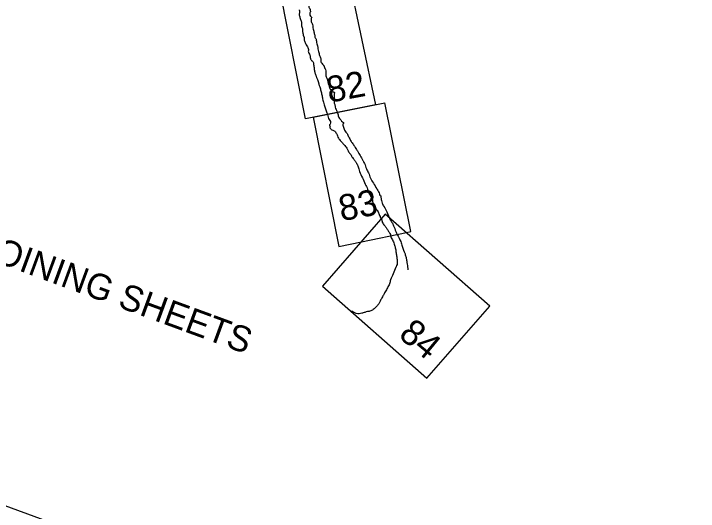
# Model space of a CAD drawing. Extents: x 3972907 to 3994831, y 172639 to 190852.
# Drawn here: x 3985354 to 3986903, y 175090 to 176216 of the extents above; entities that cross this region are included whole.
import ezdxf

# ---------------------------------------------------------------- set-up
doc = ezdxf.new("R2010")
doc.units = 0
doc.layers.add('V-ANNO-NPLT', color=7, linetype='Continuous')
doc.layers.add('V-ANNO-SYMB', color=7, linetype='Continuous')

msp = doc.modelspace()

# ---------------------------------------------------------------- linework, layer by layer
at = {"layer": 'V-ANNO-NPLT'}
for points in [[(3986110.6, 176302.8), (3986172.1, 176009.6)], [(3986172.1, 176009.6), (3986013.8, 175977.8), (3985956, 176271.3)], [(3986031.4, 175981.3), (3986193.6, 176013.9)], [(3986242.5, 175720.6), (3986252.5, 175722.7), (3986193.6, 176013.9)], [(3986031.4, 175981.3), (3986089.5, 175688.8), (3986140.4, 175699.4)], [(3986052.4, 175599.3), (3986288.5, 175391.1), (3986430.6, 175554), (3986194.4, 175762.3)], [(3986194.4, 175762.3), (3986052.4, 175599.3)], [(3986140.4, 175699.4), (3986242.5, 175720.6)]]:
    msp.add_lwpolyline(points, dxfattribs=at)
for points in [[(3986016.7, 176284.5), (3986015.7, 176281.3), (3986016.1, 176279.5), (3986016.4, 176274), (3986016.2, 176269.2), (3986016.3, 176264.6), (3986017.3, 176260.4), (3986017.7, 176257.3), (3986018.7, 176251.5), (3986020, 176246.4), (3986020.9, 176243.1), (3986021.1, 176239.5), (3986021.3, 176235.9), (3986021.3, 176230.2), (3986022.8, 176228), (3986023.8, 176227.1), (3986024.7, 176222.9), (3986024.9, 176220.1), (3986023.8, 176217.3), (3986023.4, 176214.2), (3986024.8, 176210.2), (3986026.9, 176208.5), (3986027.9, 176207.6), (3986027, 176204.7), (3986026.5, 176202.7), (3986026.4, 176200.9), (3986026.4, 176199.6)], [(3985999.6, 176224), (3986000, 176222.6), (3986000.1, 176220.7), (3986000.2, 176218.1), (3986000.1, 176217.2), (3985999.7, 176215.6)], [(3985999.7, 176215.6), (3985999.5, 176214.2), (3985999.7, 176212.5), (3986000.8, 176208.5), (3986001.8, 176204.7), (3986003.2, 176200.6), (3986004.6, 176196.8), (3986004.7, 176190.6), (3986005.8, 176185.8), (3986006.7, 176181.9), (3986007, 176179.1), (3986006.8, 176177.3)], [(3986026.4, 176199.7), (3986027.6, 176196), (3986028.8, 176193.6), (3986030.2, 176188.2), (3986030.6, 176183.7), (3986031.9, 176178.1), (3986032.8, 176174.7), (3986033.7, 176170.6), (3986034.6, 176166.8), (3986034.9, 176164.2), (3986036, 176161.3), (3986037.9, 176157.9), (3986038.2, 176155.3), (3986038.5, 176153.9)], [(3986006.8, 176177.3), (3986007.3, 176174.2), (3986007.8, 176171.2), (3986008.8, 176167.7), (3986009.1, 176165.4), (3986009.9, 176164.2)], [(3986009.9, 176164.2), (3986010.5, 176162.7), (3986010.5, 176159.2), (3986011, 176155.8), (3986012.3, 176152), (3986015.4, 176144.9), (3986018.2, 176140.8), (3986019.8, 176136.7), (3986020.6, 176133.1), (3986020, 176130.9), (3986021.6, 176126), (3986023.7, 176121.6), (3986024.3, 176118.4), (3986024.5, 176117)], [(3986038.5, 176153.9), (3986039.5, 176147.7), (3986041, 176142.5), (3986042.1, 176136.4), (3986043.5, 176130.2), (3986045.6, 176121), (3986047.8, 176115.5), (3986048.7, 176112.4), (3986048.8, 176106.5), (3986050.7, 176103.6), (3986054, 176099.6), (3986054.8, 176098.7), (3986056.6, 176097.2)], [(3986024.5, 176117), (3986024.8, 176114.9), (3986026, 176112.3), (3986027.5, 176109.9), (3986028.8, 176108.6), (3986029.9, 176107.9)], [(3986029.9, 176107.9), (3986030.4, 176107.3), (3986031.7, 176104.3), (3986032.3, 176100.3), (3986033, 176096.5), (3986033.6, 176091.2), (3986034.6, 176083.4), (3986037.1, 176076.5), (3986037.7, 176073.9), (3986040.2, 176068.6), (3986043.1, 176060.1), (3986043.7, 176057.5), (3986044.6, 176054.1), (3986045.4, 176052)], [(3986055.9, 176097.8), (3986056.4, 176095.6), (3986057.2, 176092.8), (3986059.2, 176089), (3986059.6, 176084.3), (3986059.5, 176080), (3986060, 176075), (3986061.8, 176069.9), (3986063.8, 176064.6), (3986064.7, 176060.7), (3986066.4, 176053.8), (3986067.9, 176048.6), (3986069.7, 176045), (3986072.2, 176043.7), (3986073, 176041)], [(3986045.4, 176052), (3986048.1, 176043.6), (3986050.3, 176034.6), (3986052.1, 176025.5), (3986054.6, 176015.1), (3986056.3, 176009.1), (3986059, 176000.7), (3986062.2, 175991.6), (3986063.3, 175987.4), (3986065.3, 175981.5), (3986067.1, 175976.4), (3986070.3, 175971.4), (3986069.8, 175965.9), (3986068.3, 175964.1), (3986068.7, 175961.8), (3986069.3, 175960.5)], [(3986073, 176041), (3986075.6, 176038.6), (3986077.2, 176038.5), (3986078.8, 176037.9), (3986079.2, 176036.1), (3986078.8, 176033), (3986078.8, 176029.5), (3986078.8, 176023.8), (3986078.6, 176018.5), (3986078.8, 176013.5), (3986080.9, 176007.1), (3986081, 176003.8), (3986082.9, 175999), (3986084.3, 175996.3), (3986086.1, 175991.3), (3986087.8, 175986.5), (3986088.4, 175982.5), (3986093.5, 175975.4), (3986095.5, 175972.4), (3986099.5, 175969.5)], [(3986069.3, 175960.5), (3986069.1, 175957.7), (3986070.1, 175956), (3986072.2, 175953.8), (3986078.8, 175950.7), (3986081.4, 175948.3), (3986084, 175944.3), (3986086.3, 175939.1), (3986088.6, 175934.1), (3986090.7, 175931.2), (3986094, 175926.9), (3986097.4, 175923.4), (3986099.6, 175920.7), (3986102.9, 175917.3), (3986106, 175913.4), (3986108.4, 175910), (3986109.7, 175907), (3986113.6, 175900.4), (3986115.2, 175898.9), (3986116.9, 175895.6), (3986118.9, 175891.8), (3986121.4, 175888.4), (3986124.3, 175884.9), (3986126.3, 175882.2), (3986127.6, 175880.1), (3986129.1, 175877.6), (3986129.6, 175876.9)], [(3986099.5, 175969.5), (3986099.7, 175968.8), (3986099.9, 175967.4), (3986098.6, 175965.4), (3986099.1, 175961.2), (3986100.2, 175957), (3986102.1, 175952.2), (3986105, 175947.8), (3986108.9, 175943.1), (3986110.7, 175938.8), (3986112.9, 175934.7), (3986115, 175930.4), (3986116.8, 175926.7), (3986119.4, 175923.6), (3986122.4, 175919.4), (3986126.3, 175912.8), (3986129, 175908.7), (3986131.2, 175905.2), (3986134.4, 175899.1), (3986137.9, 175894.7), (3986140.2, 175889.5), (3986143.4, 175883.9), (3986144.7, 175881.6)], [(3986144.7, 175881.6), (3986147.5, 175877), (3986151.8, 175865), (3986156.3, 175855.9), (3986160.9, 175843.3), (3986167.5, 175832.4), (3986175.1, 175819.4), (3986179.2, 175812.5), (3986181.1, 175807.7), (3986184.4, 175803.7), (3986184.8, 175803.7)], [(3986129.6, 175876.9), (3986132.7, 175869.5), (3986134.4, 175864.7), (3986136.1, 175858.7), (3986142.5, 175844.6), (3986148.8, 175830.2), (3986154.4, 175818.8), (3986157.4, 175810.1), (3986161.2, 175803.2), (3986164.4, 175796.8), (3986165.7, 175790.4)], [(3986184.6, 175803.7), (3986184.7, 175797), (3986185.5, 175793.3), (3986187, 175787.4), (3986191.4, 175779.3), (3986197.5, 175767.8), (3986201.5, 175758.7), (3986203.6, 175753.4), (3986209.2, 175743.6), (3986213.3, 175735.7), (3986218.3, 175723.2), (3986221.5, 175715.9)], [(3986165.7, 175790.4), (3986167.1, 175787.6), (3986169.1, 175784.9), (3986170.4, 175782.5), (3986171.2, 175779.6), (3986171.6, 175776.8), (3986174.7, 175772.2), (3986176.7, 175769.5), (3986179.1, 175765.2), (3986180.7, 175761.5), (3986182.4, 175757.1), (3986183.4, 175753.7), (3986185.7, 175750.9), (3986186.6, 175747.5), (3986187.6, 175744.1), (3986189.8, 175740.2), (3986192.5, 175736.5), (3986194.2, 175735.3)], [(3986194.2, 175735.3), (3986198.2, 175728.8), (3986201.7, 175723.3), (3986205.8, 175716.4), (3986207.7, 175708.8), (3986210.4, 175704.4), (3986214.2, 175694.4), (3986217, 175685.8), (3986218.5, 175677.2), (3986219.8, 175668.1), (3986220.9, 175659.7), (3986221.3, 175653), (3986220.9, 175648.3), (3986218.9, 175643.2), (3986218.5, 175642.2)], [(3986221.5, 175715.9), (3986229.2, 175700.2), (3986232.7, 175689.8), (3986239, 175672.2), (3986241.5, 175664.1), (3986242.9, 175656), (3986244.9, 175642.8), (3986245.7, 175636)], [(3986218.5, 175642.2), (3986212.2, 175627.1), (3986206.2, 175613.6), (3986204.1, 175604.5), (3986199.1, 175595.6), (3986194.2, 175586.3), (3986191.5, 175582.3), (3986190.4, 175579.2)], [(3986190.4, 175579.2), (3986185.5, 175570.9), (3986181.8, 175564), (3986178.6, 175558.2), (3986174.6, 175553.4), (3986168.9, 175548.1), (3986161.4, 175543.2), (3986154.2, 175541.7), (3986148.2, 175540.1), (3986141.1, 175538), (3986135.1, 175536.9), (3986128.8, 175537.6), (3986122.3, 175540.7), (3986119, 175543.1)]]:
    msp.add_spline(points, degree=3, dxfattribs=at)
at = {"layer": 'V-ANNO-SYMB'}
msp.add_lwpolyline([(3974579.2, 179056.1), (3990105.3, 173349.5), (3994058.3, 184104.4), (3978532.2, 189811), (3974579.2, 179056.1)], dxfattribs=at)

# ---------------------------------------------------------------- texts
at = {"layer": 'V-ANNO-NPLT'}
for s, height, rotation, p in [('82', 58.5, 10.531, (3986067.4, 176014.1)), ('INDEX TO ADJOINING SHEETS', 58.33, 339.8191, (3984801.6, 175841.5)), ('83', 58.5, 10.531, (3986094.9, 175746.1)), ('84', 58.5, 320.531, (3986221.9, 175485.2))]:
    msp.add_text(s, height=height, rotation=rotation, dxfattribs=at).set_placement(p)

doc.saveas('drawing.dxf')
